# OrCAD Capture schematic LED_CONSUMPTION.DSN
size A
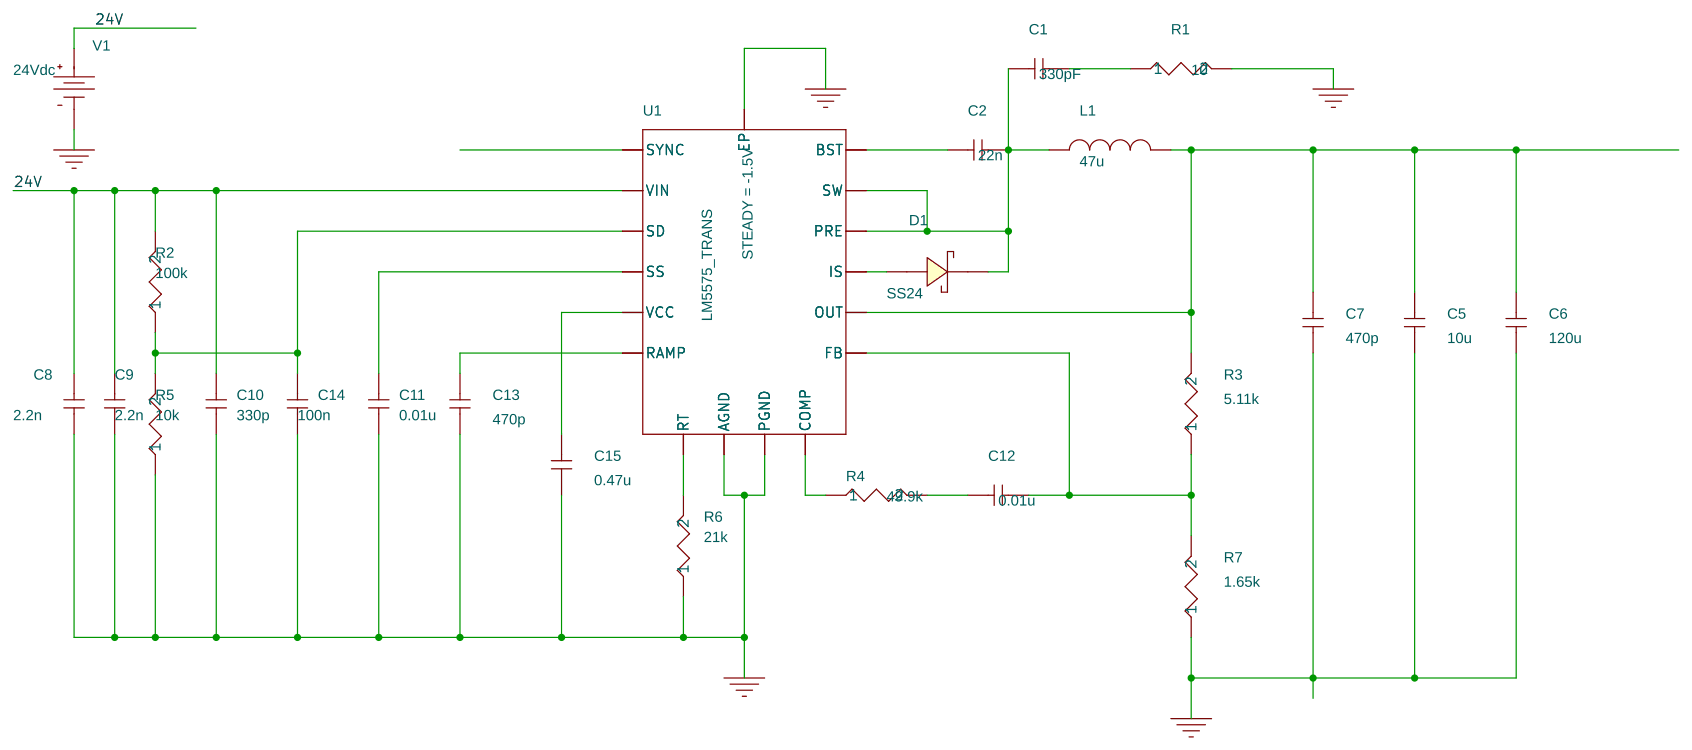
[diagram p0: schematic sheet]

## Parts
C1  330pF  [CK05]
C2  22n  [CK05]
C5  10u  [CK05]
C6  120u  [CK05]
C7  470p  [CK05]
C8  2.2n  [CK05]
C9  2.2n  [CK05]
C10  330p  [CK05]
C11  0.01u  [CK05]
C12  0.01u  [CK05]
C13  470p  [CK05]
C14  100n  [CK05]
C15  0.47u  [CK05]
D1  SS24  [SMB403A]
L1  47u  [DISC/.350x.175/LS.200x.100/.034]
R1  10
R2  100k
R3  5.11k
R4  49.9k
R5  10k
R6  21k
R7  1.65k
U1  LM5575_TRANS
V1  VDC

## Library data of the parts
C1 C2 C5-C15 = C
D1 = SS24
L1 = l
R1 = R_6
R2 = R_2
R3 = R_3
R4 = R
R5 = R_1
R6 = R_4
R7 = R_5
U1 = LM5575_TRANS_1: STEADY: -1.5V
V1 = VDC: DC: 24Vdc

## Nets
24V: C8.2 C9.2 C10.2 R2.2 U1.VIN V1.0(+)
0: C5.1 C6.1 C7.1 C8.1 C9.1 C10.1 C11.1 C13.1 C14.1 C15.1 R1.2 R5.1 R6.1 R7.1 U1.AGND U1.EP U1.PGND V1.1(-)
N01229: C2.1 U1.BST
N01233: C1.1 C2.2 D1.1(C) L1.1 U1.PRE U1.SW
N01237: C1.2 R1.1
N07134: C5.2 C6.2 C7.2 L1.2 R3.2 U1.OUT
N07209: D1.2(A) U1.IS
N07351: R4.1 U1.COMP
N07384: C12.2 R3.1 R7.2 U1.FB
N07474: C12.1 R4.2
N07922: R6.2 U1.RT
N08053: C13.2 U1.RAMP
N08060: C15.2 U1.VCC
N08098: C11.2 U1.SS
N08313: C14.2 R2.1 R5.2 U1.SD

Not connected (* = marked no-connect by the designer): U1 SYNC
